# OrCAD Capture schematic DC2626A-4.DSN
size Custom; company: ANALOG DEVICES; note: DEMO BOARD BILL OF MATERIALS; note: HIGH POWER SYNCHRONOUS 4-SWITCH BUCK-BOOST
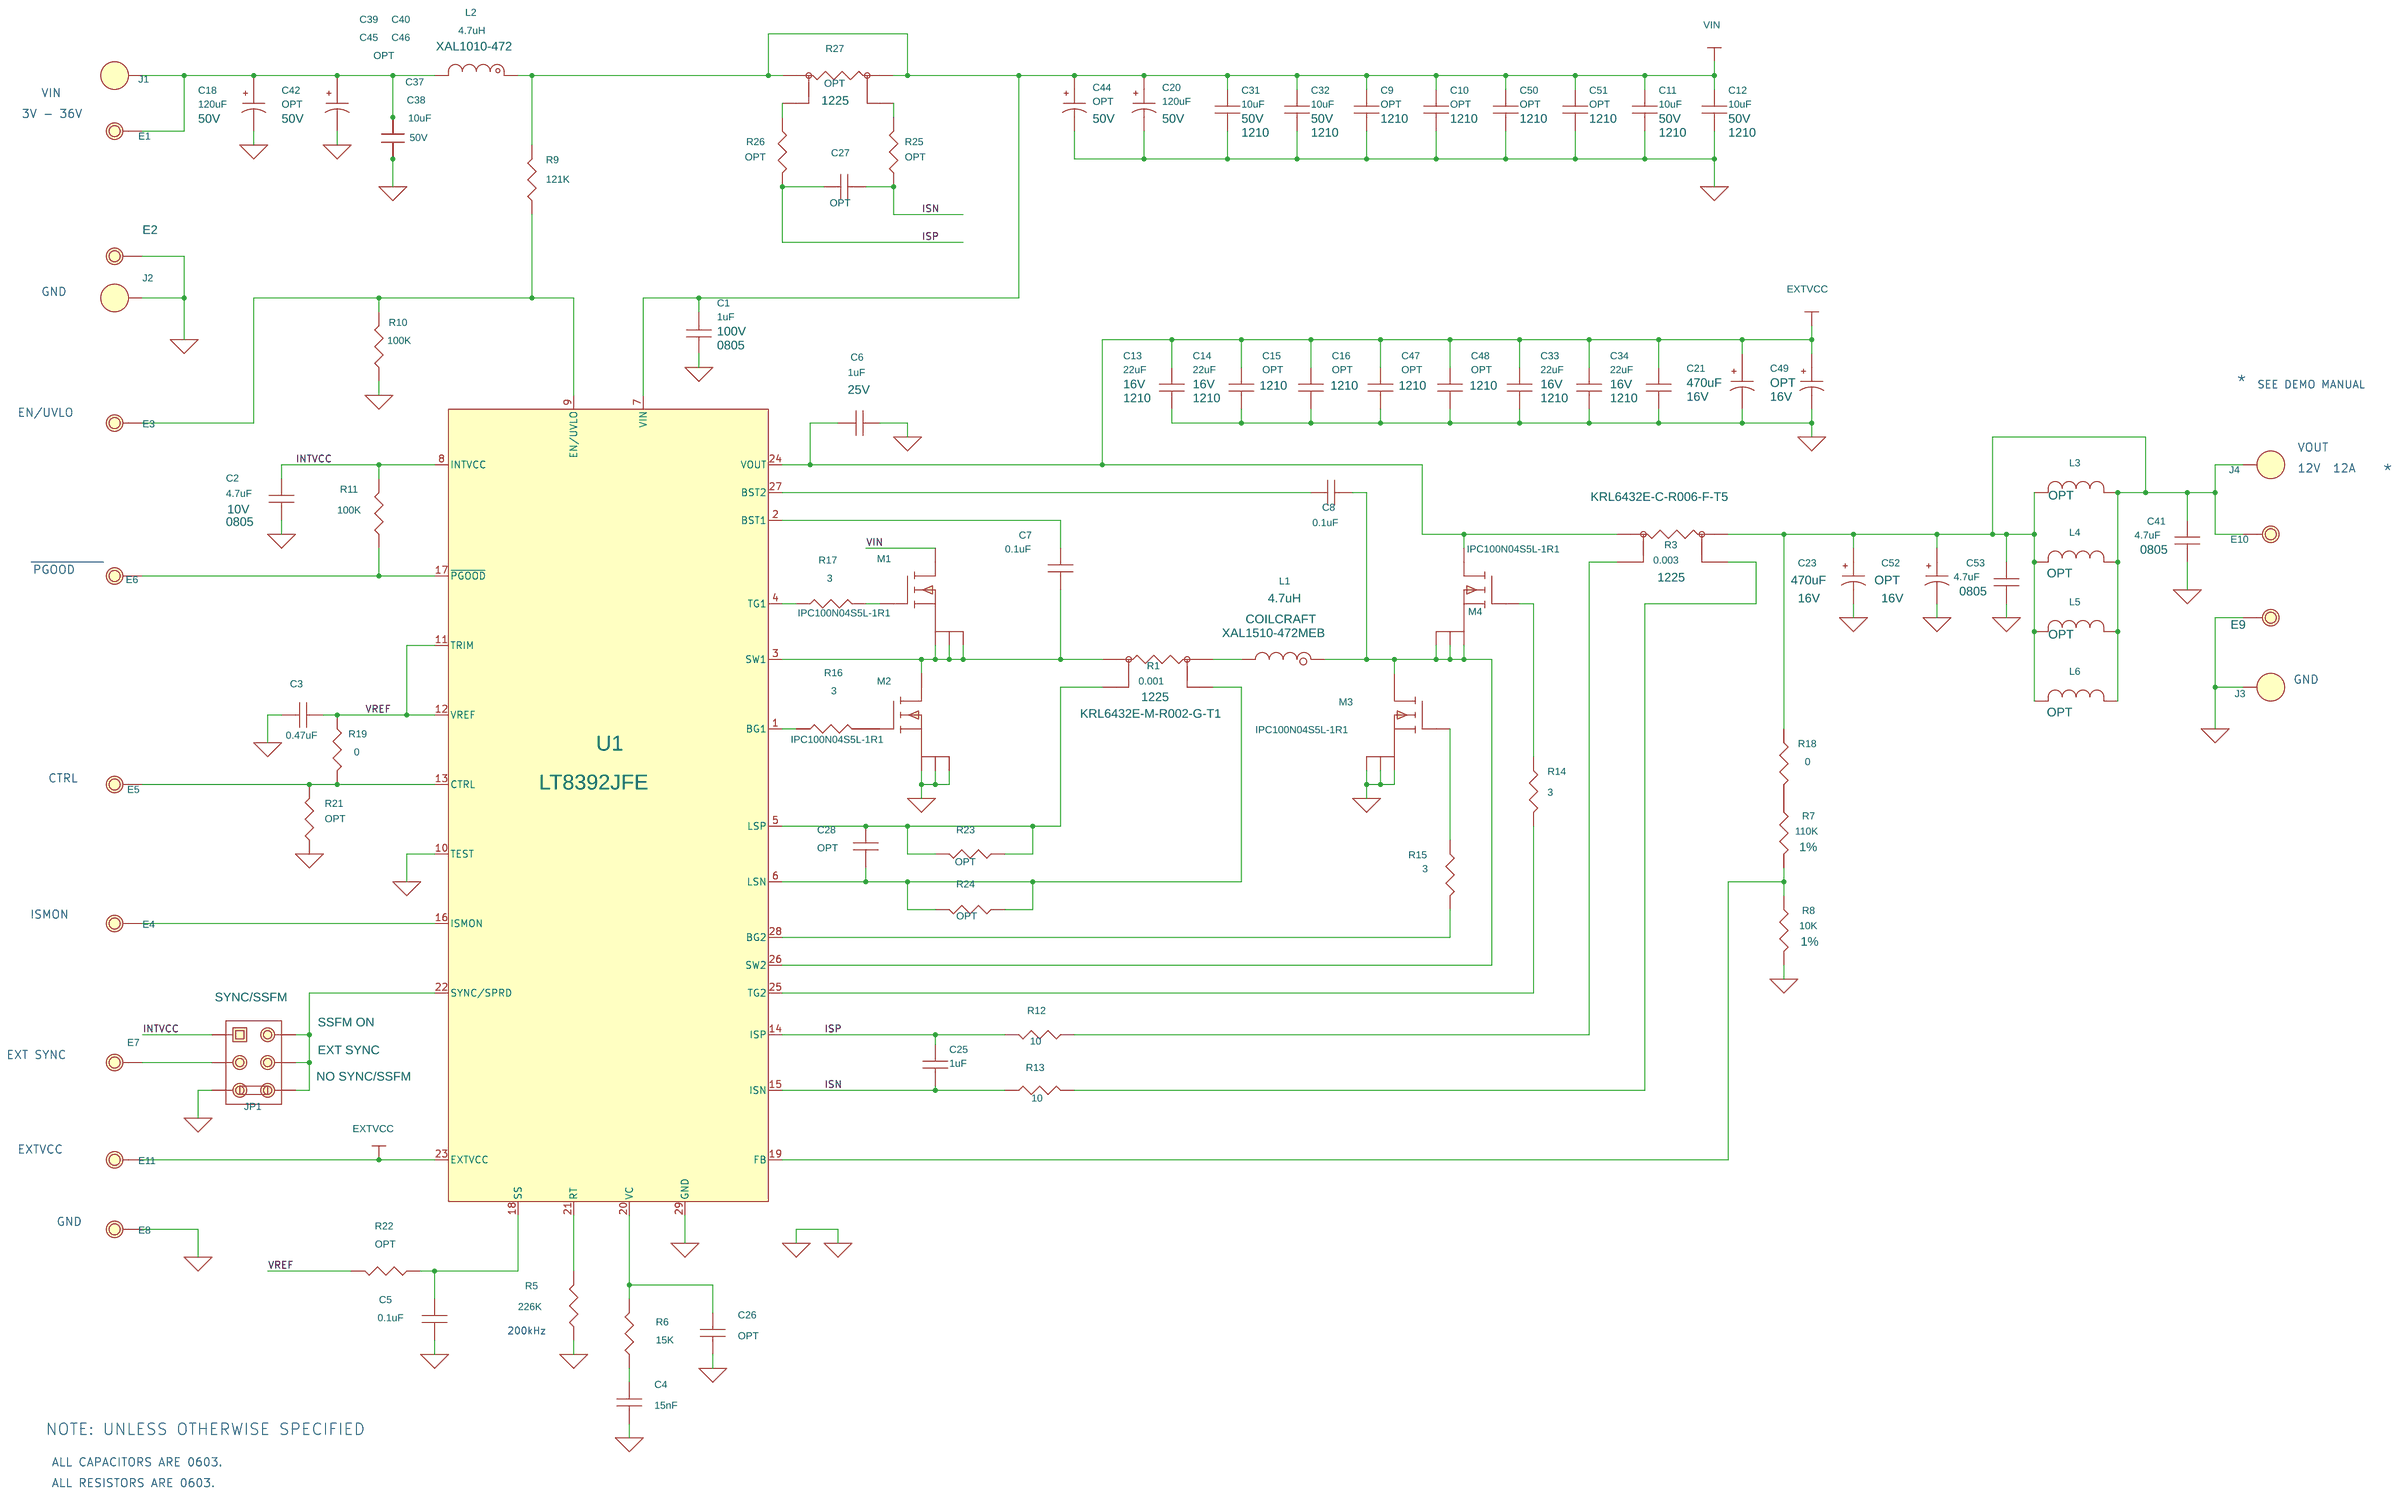
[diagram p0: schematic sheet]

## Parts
C1  1uF  [0805]
C2  4.7uF  [0805]
C3  0.47uF  [0603]
C4  15nF  [0603]
C5  0.1uF  [0603]
C6  1uF  [0603]
C7  0.1uF  [0603]
C8  0.1uF  [0603]
C9  OPT  [1210]
C10  OPT  [1210]
C11  10uF  [1210]
C12  10uF  [1210]
C13  22uF  [1210]
C14  22uF  [1210]
C15  OPT  [1210]
C16  OPT  [1210]
C18  120uF  [CAP-CE-10x10.2]
C20  120uF  [CAP-CE-10x10.2]
C21  470uF  [CAP-CE-10x10.2]
C23  470uF  [CAP-CE-10x10.2]
C25  1uF  [0603]
C26  OPT  [0603]
C27  OPT  [0603]
C28  OPT  [0603]
C31  10uF  [1210]
C32  10uF  [1210]
C33  22uF  [1210]
C34  22uF  [1210]
C37  10uF  [1210]
C38  10uF  [1210]
C39  OPT  [1210]
C40  OPT  [1210]
C41  4.7uF  [CC0805N]
C42  OPT  [CAP-CE-10x10.2]
C44  OPT  [CAP-CE-10x10.2]
C45  OPT  [1210]
C46  OPT  [1210]
C47  OPT  [1210]
C48  OPT  [1210]
C49  OPT  [CAP-CE-10x10.2]
C50  OPT  [1210]
C51  OPT  [1210]
C52  OPT  [CAP-CE-10x10.2]
C53  4.7uF  [CC0805N]
E1  Testpoint  [MM/2501]
E2  Testpoint  [MM/2501]
E3  Testpoint  [MM/2501]
E4  Testpoint  [MM/2501]
E5  Testpoint  [MM/2501]
E6  Testpoint  [MM/2501]
E7  Testpoint  [MM/2501]
E8  Testpoint  [MM/2501]
E9  Testpoint  [MM/2501]
E10  Testpoint  [MM/2501]
E11  Testpoint  [MM/2501]
J1  BANANA-JACK  [KEY-575-4]
J2  BANANA-JACK  [KEY-575-4]
J3  BANANA-JACK  [KEY-575-4]
J4  BANANA-JACK  [KEY-575-4]
JP1  3 Pins 2mm Ctrs.  [JP3X2/079]
L1  4.7uH  [IND-XAL1510]
L2  4.7uH  [IND-XAL1010]
L3  7427922  [IND-7427922]
L4  7427922  [IND-7427922]
L5  7427922  [IND-7427922]
L6  7427922  [IND-7427922]
M1  IPC100N04S5L-1R1  [PG-TDSON-8-F]
M2  IPC100N04S5L-1R1  [PG-TDSON-8-F]
M3  IPC100N04S5L-1R1  [PG-TDSON-8-F]
M4  IPC100N04S5L-1R1  [PG-TDSON-8-F]
R1  0.001  [1225]
R3  0.003  [1225]
R5  226K  [0603]
R6  15K  [0603]
R7  110K  [0603]
R8  10K  [0603]
R9  121K  [0603]
R10  100K  [0603]
R11  100K  [0603]
R12  10  [0603]
R13  10  [0603]
R14  3  [0603]
R15  3  [0603]
R16  3  [0603]
R17  3  [0603]
R18  0  [0603]
R19  0  [0603]
R21  OPT  [0603]
R22  OPT  [0603]
R23  OPT  [0603]
R24  OPT  [0603]
R25  OPT  [0603]
R26  OPT  [0603]
R27  OPT  [1225]
U1  LT8392JFE  [TSSOP28FE-EB]
XJP1  2mm Ctrs.

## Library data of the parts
C1 = CAP_NP: 2nd Part Field: 10%; 7th Part Field: CAP.,; Voltage: 100V
C2 = CAP_NP: 2nd Part Field: 10%; 7th Part Field: CAP.,; Voltage: 10V
C3-C5 C7 C8 C25-C28 = CAP_NP: 2nd Part Field: 10%; 7th Part Field: CAP.,; Voltage: 6.3V
C6 = CAP_NP: 2nd Part Field: 10%; 7th Part Field: CAP.,; Voltage: 25V
C9-C12 C31 C32 C50 C51 = CAP_NP: 2nd Part Field: 10%; 7th Part Field: CAP.,; Voltage: 50V
C13-C16 C33 C34 C47 C48 = CAP_NP: 1st Part Field: 16V; 2nd Part Field: 10%; 4th Part Field: MURATA; 5th Part Field: GRM32ER61C476KE15K; 7th Part Field: CAP.,; Voltage: 16V
C18 C20 C42 C44 = 16TQC47M: 1st Part Field: 50V; 2nd Part Field: 20%; 4th Part Field: NICHICON; 5th Part Field: PCR1H181MCL1GS; 7th Part Field: CAP.,
C21 C49 = 16TQC47M: 1st Part Field: 16V; 2nd Part Field: 20%; 4th Part Field: SUN ELEC.; 5th Part Field: 16HVH560M; 7th Part Field: CAP.,; Voltage: 16V
C23 C52 = 16TQC47M: 1st Part Field: 16V; 2nd Part Field: 20%; 4th Part Field: SUN ELEC.; 5th Part Field: 16HVH560M; 7th Part Field: CAP.,
C37-C40 C45 C46 = CAP1210: 1ST PART FIELD: 50V
C41 C53 = CAP: CAP.,4.7uF,X7R,16V,10%,0805; CLASS: DISCRETE; Dielectric Type: X7R; FPLIST: CC0805N,CC0805L,CC0805M; Inventory Qty: 57178; Manufacturer: AVX; Manufacturer PN: 0805YC475KAT2A; PART_NUMBER: 150-2085; Package Size: 0805; Rated Voltage: 16V; Tolerance: 10%
E1-E5 E7-E11 = MillMax-2501-2_1: V: GND
E6 = MillMax-2501-2_0: V: GND
J1-J4 = BANANA-JACK: 8th Part Field: 4V - 50V; 9th Part Field: PVIN
JP1 = Samtec_TMM-104-02-L-S_9: 10th Part Field: EXT SYNC; 11th Part Field: NO SYNC/SSFM; 13tht Part Field: SYNC/SSFM; 9th Part Field: SSFM ON
L1 = INDUCTOR_0: 4th Part Field: COILCRAFT; 5th Part Field: XAL1510-472MEB; 7th Part Field: INDUCTOR
L2 = IND_1: 5th Part Field: XAL1010-472
L3-L6 = IND: 4th Part Field: OPT
M1-M4 = MOS_FET_9
R1 = LRC1206-SENSE_0: 1st Part Field: 3W; 4th Part Field: SUSUMU; 5th Part Field: KRL6432E-M-R002-G-T1; 7th Part Field: RES.,
R3 = LRC1206-SENSE_0: 1st Part Field: 3W; 4th Part Field: SUSUMU; 5th Part Field: KRL6432E-C-R006-F-T5; 7th Part Field: RES.,
R5-R19 R21 R23-R26 = RESISTOR: 2nd Part Field: 1%; 7th Part Field: RES.,
R22 = RESISTOR_1: 2nd Part Field: 1%; 7th Part Field: RES.,
R27 = LRC1206-SENSE_0: 7th Part Field: RES.,
U1 = LT3791EFE_40
XJP1 = Samtec_2SN-BK-G_1

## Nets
GND: C1.1 C2.2 C3.2 C4.2 C5.2 C6.1 C9.2 C10.2 C11.2 C12.2 C13.2 C14.2 C15.2 C16.2 C18.2 C20.2 C21.2 C23.2 C26.2 C31.2 C32.2 C33.2 C34.2 C37.2 C38.2 C39.2 C40.2 C41.2 C42.2 C44.2 C45.2 C46.2 C47.2 C48.2 C49.2 C50.2 C51.2 C52.2 C53.2 E2.1 E8.1 E9.1 J2.1 J3.1 JP1.5 M2.1(S) M2.2(S) M2.3(S) M3.1(S) M3.2(S) M3.3(S) R5.2 R8.2 R10.2 R21.2 U1.10(TEST) U1.29(GND)
VIN: C1.2 C9.1 C10.1 C11.1 C12.1 C20.1 C31.1 C32.1 C44.1 C50.1 C51.1 L2.1 M1.5(D) R9.1 R27.1 R27.3 U1.7(VIN)
EXTVCC: C6.2 C13.1 C14.1 C15.1 C16.1 C21.1 C33.1 C34.1 C47.1 C48.1 C49.1 E11.1 M4.5(D) R3.3 U1.23(EXTVCC) U1.24(VOUT)
INTVCC: C2.1 JP1.1 R11.1 U1.8(INTVCC)
ISN: C25.2 C27.2 R13.1 R25.1 U1.15(ISN)
ISP: C25.1 C27.1 R12.1 R26.1 U1.14(ISP)
VREF: C3.1 R19.2 R22.2 U1.11(TRIM) U1.12(VREF)
N16994718: C7.1 U1.2(BST1)
N17009346: C4.1 R6.2
N17028240: C7.2 M1.1(S) M1.2(S) M1.3(S) M2.5(D) R1.1 U1.3(SW1)
N17092217: R3.2 R13.2
N17395809: E3.1 R9.2 R10.1 U1.9(EN/UVLO)
N17454578: C28.1 R1.2 R23.1 R23.2 U1.5(LSP)
N17457653: R3.4 R12.2
N17465905: C8.2 L1.1 M3.5(D) M4.1(S) M4.2(S) M4.3(S) U1.26(SW2)
N17508110: R16.1 U1.1(BG1)
N17509789: R17.1 U1.4(TG1)
N17527032: C28.2 R1.4 R24.1 R24.2 U1.6(LSN)
N17708049: C23.1 C41.1 C52.1 C53.1 E10.1 J4.1 L3.1 L3.2 L4.1 L4.2 L5.1 L5.2 L6.1 L6.2 R3.1 R18.1
N17718651: M4.4(G) R14.1
N17732267: C8.1 U1.27(BST2)
N17732582: M1.4(G) R17.2
N17804277: C18.1 C37.1 C38.1 C39.1 C40.1 C42.1 C45.1 C46.1 E1.1 J1.1 L2.2
N17841959: E6.1 R11.2 U1.17(~{PGOOD})
N17844598: E4.1 U1.16(ISMON)
N17844661: JP1.2 JP1.4 JP1.6 U1.22(SYNC/SPRD)
N17844682: E7.1 JP1.3
N17845406: C5.1 R22.1 U1.18(SS)
N17868485: C26.1 R6.1 U1.20(VC)
N17869628: R7.2 R8.1 U1.19(FB)
N17943326: L1.2 R1.3
N17974207: R26.2 R27.4
N17974209: R25.2 R27.2
N18003623: M3.4(G) R15.1
N18007219: E5.1 R19.1 R21.1 U1.13(CTRL)
N18097849: R7.1 R18.2
N18097851: M2.4(G) R16.2
N18377159: R15.2 U1.28(BG2)
N18382365: R14.2 U1.25(TG2)
N18452641: R5.1 U1.21(RT)

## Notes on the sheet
- VIN
- 3V - 36V
- GND
- *
- SEE DEMO MANUAL
- EN/UVLO
- VOUT
- 12V  12A
- *
- PGOOD
- GND
- CTRL
- ISMON
- EXT SYNC
- EXTVCC
- GND
- 200kHz
- NOTE: UNLESS OTHERWISE SPECIFIED
- ALL CAPACITORS ARE 0603.
- ALL RESISTORS ARE 0603.
